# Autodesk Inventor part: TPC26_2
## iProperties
Shininess: 64.0
Length Units: 11272
Angle Units: 11279
Time Units: 11290
Mass Units: 11286
Length Display Precision: 3
Angle Display Precision: 2
Compacted: True
Part Number: TPC26_2
Document SubType Name: Modeling
Created: 2004-08
Designer: Lori
Manufacturer: Standard
Standards Organization: Custom
Density: 0.0
Volumn: 0.0
Area: 0.0
PropertySet Name: Model Information
Control State: 0
Master: False
Checked Out: False
Author: Lori
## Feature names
1. Base1
